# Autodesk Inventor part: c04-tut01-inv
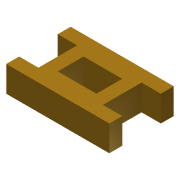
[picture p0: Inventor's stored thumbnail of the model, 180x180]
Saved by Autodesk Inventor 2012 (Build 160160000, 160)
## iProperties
Created: 2010-01
Part Number: c04-tut01-inv
Document SubType Name: Modeling
Designer: CADSoft
Density: 1 g/cm^3
Material: Default
Author: CADSoft
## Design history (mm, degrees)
sketch "Sketch1"
  geometry: L1 (80, 0)-(0, 0); L2 (0, 0)-(0, 10); L3 (0, 10)-(15, 10); L4 (15, 10)-(15, 40); L5 (15, 40)-(0, 40); L6 (0, 40)-(0, 50); L7 (0, 50)-(80, 50); L8 (80, 50)-(80, 40); L9 (80, 40)-(65, 40); L10 (65, 40)-(65, 10); L11 (65, 10)-(80, 10); L12 (80, 10)-(80, 0); L13 (25, 35)-(55, 35); L14 (55, 35)-(55, 15); L15 (55, 15)-(25, 15); L16 (25, 15)-(25, 35); 2 further points
  constraints: 32 end point, 9 equal length, 7 horizontal, 6 vertical, 2 coincident, 1 other
  dimensions: "d1" = 80 distance of L1.start L1.end; "d2" = 10 distance of L1.end L2.end; "d3" = 30 distance of L3.end L4.end; "d4" = 20 distance of L13.end L14.end; "d5" = 30 distance of L13.start L13.end; "d6" = 10 distance between parallel lines of L16 L4; "d7" = 10 distance between parallel lines of L10 L14; "d8" = 15 distance between parallel lines of L15 L1
extrude "Extrusion1" new body sketch "Sketch1" distance "d9" = 20; taper "d10" = 0 deg
body "Solid1"
